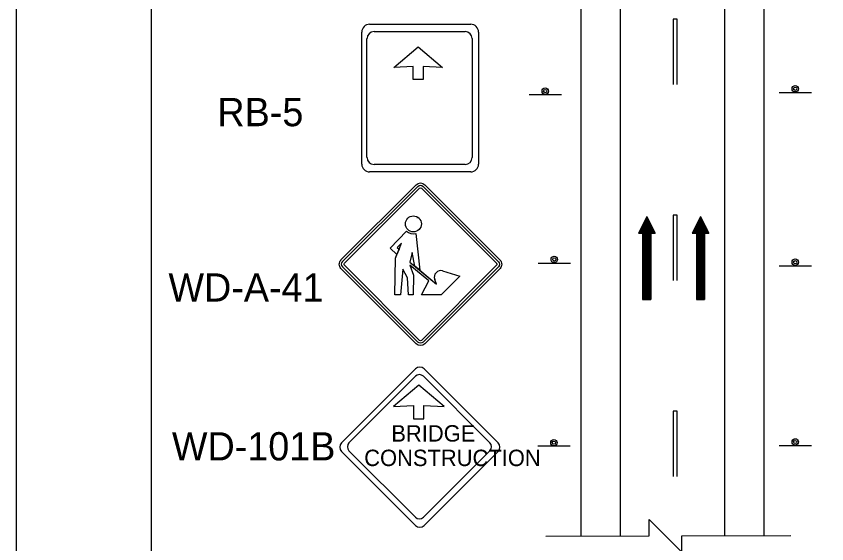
# Model space of a CAD drawing. Extents: x 2157 to 2399, y 147 to 426.
# Drawn here: x 2182.7 to 2242.8, y 199.6 to 238.6 of the extents above; entities that cross this region are included whole.
import ezdxf

# ---------------------------------------------------------------- set-up
doc = ezdxf.new("R2010")
doc.units = 0
for name, color, linetype in [('Level 1', 7, 'Continuous'), ('Level 10', 7, 'Continuous'), ('Level 20', 7, 'Continuous'), ('Level 44', 7, 'Continuous'), ('Level 60', 7, 'Continuous')]:
    doc.layers.add(name, color=color, linetype=linetype)

# ---------------------------------------------------------------- blocks, each defined once
blk = doc.blocks.new('2_95')
at = {"layer": 'Level 1'}
for points in [[(18.2, 120.1), (22.8, 116.1), (17.2, 102.4), (0, 118.7), (41.5, 161.7)], [(18.2, 120.1), (22.8, 116.1), (17.2, 102.4), (0, 118.7), (41.5, 161.7)], [(32.4, 65), (26.3, 0), (11.7, 0), (13.7, 93.4), (17.3, 102.4), (0, 118.7), (41.5, 161.7)], [(65.4, 155.5), (75, 62.6), (62.6, 72.8), (55.6, 107.5), (49.8, 83.3), (117.7, 27.3), (113, 39.4)], [(65.4, 155.5), (75, 62.6), (62.6, 72.8), (55.6, 107.5), (49.8, 83.3), (117.7, 27.3), (113, 39.4)], [(65.4, 155.5), (75, 62.5), (117.7, 27.3), (113, 39.4)], [(132.9, 60.9), (176.6, 47.8), (129.3, 0), (79.5, 0), (98.2, 36), (49.8, 75.6), (59.3, 50.4), (58, 0), (46.2, 0), (44, 43), (32.4, 65), (26.3, 0), (11.7, 0), (13.7, 93.4), (28.7, 130.9), (18.2, 120.1)], [(132.9, 60.9), (176.6, 47.8), (129.3, 0), (79.5, 0), (98.2, 36), (49.8, 75.6), (59.3, 50.4), (58, 0), (46.2, 0), (44, 43), (32.4, 65), (26.3, 0), (11.7, 0), (13.7, 93.4), (28.7, 130.9), (18.2, 120.1)], [(132.9, 60.9), (176.6, 47.8), (129.3, 0), (79.5, 0), (98.2, 36), (49.8, 75.6), (59.3, 50.4), (58, 0), (46.2, 0), (44, 43), (32.4, 65)]]:
    blk.add_lwpolyline(points, dxfattribs=at)
for points in [[(18.2, 120.1), (22.8, 116.1), (28.7, 130.9)], [(62.6, 72.8), (55.6, 107.5), (49.8, 83.3)]]:
    blk.add_lwpolyline(points, close=True, dxfattribs=at)
blk.add_circle((58.9, 179.8), 20.2, dxfattribs=at)
blk.add_circle((58.9, 179.8), 20.2, dxfattribs=at)
blk.add_circle((58.9, 179.8), 20.2, dxfattribs=at)
for centre, radius, start, end in [((58.9, 179.8), 25.1, 226.3135, 284.9576), ((58.9, 179.8), 25.1, 226.3135, 284.9576), ((58.9, 179.8), 25.1, 226.3135, 284.9576), ((128.2, 45.3), 16.3, 73.381, 201.0999), ((128.2, 45.3), 16.3, 73.381, 201.0999), ((128.2, 45.3), 16.3, 73.381, 201.0999)]:
    blk.add_arc(centre, radius, start, end, dxfattribs=at)
blk = doc.blocks.new('WDA41')
at = {"layer": 'Level 1'}
for p, q in [((-6.546, 0.348), (-0.352, 6.542)), ((-6.408, 0.21), (-0.215, 6.404)), ((-6.271, 0.073), (-0.077, 6.267)), ((0.072, 6.267), (6.27, 0.077)), ((0.21, 6.405), (6.408, 0.214)), ((0.348, 6.543), (6.545, 0.352)), ((0.287, 3.829), (0.303, 3.829)), ((-0.348, -6.542), (-6.546, -0.352)), ((-0.211, -6.404), (-6.408, -0.214)), ((-0.073, -6.266), (-6.27, -0.076)), ((6.27, -0.072), (0.076, -6.266)), ((6.408, -0.21), (0.214, -6.404)), ((6.546, -0.348), (0.352, -6.542))]:
    blk.add_line(p, q, dxfattribs=at)
for centre, radius, start, end in [((-0.002, 6.192), 0.495, 45.03492, 135), ((-0.002, 6.192), 0.3, 45.03492, 135), ((-0.002, 6.192), 0.105, 45.03492, 135), ((-6.196, -0.002), 0.495, 135, 225.03489), ((-6.196, -0.002), 0.3, 135, 225.03489), ((-6.196, -0.002), 0.105, 135, 225.03489), ((6.195, 0.002), 0.105, 315, 45.035), ((6.195, 0.002), 0.3, 315, 45.035), ((6.195, 0.002), 0.495, 315, 45.035), ((0.002, -6.192), 0.495, 225.03483, 315), ((0.002, -6.192), 0.3, 225.03483, 315), ((0.002, -6.192), 0.105, 225.03483, 315)]:
    blk.add_arc(centre, radius, start, end, dxfattribs=at)
at = {"layer": 'Level 1', "xscale": 0.032498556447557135, "yscale": -0.032498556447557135, "rotation": 180}
blk.add_blockref('2_95', (2.5, -2.524), dxfattribs=at)
blk = doc.blocks.new('APRNTR')
at = {"layer": 'Level 60'}
for points in [[(19.126, 268.191), (-196.874, 268.191), (-196.874, -10.809), (19.126, -10.809)], [(0, 257.382), (-186.874, 257.382), (-186.874, 0), (0, 0)]]:
    blk.add_lwpolyline(points, close=True, dxfattribs=at)

msp = doc.modelspace()

# ---------------------------------------------------------------- linework, layer by layer
at = {"layer": 'Level 10'}
for p, q in [((2224.589, 200.123), (2224.589, 338.668)), ((2238.136, 200.147), (2238.136, 338.668)), ((2227.492, 236.238), (2227.492, 302.984)), ((2235.233, 236.251), (2235.233, 284.274)), ((2231.401, 238.396), (2231.401, 233.558)), ((2231.691, 238.396), (2231.401, 238.396)), ((2231.691, 233.558), (2231.691, 238.396)), ((2227.492, 200.129), (2227.492, 236.238)), ((2235.233, 200.142), (2235.233, 236.257)), ((2229.438, 223.776), (2228.824, 222.548)), ((2229.283, 223.468), (2229.283, 217.64)), ((2229.361, 223.622), (2229.361, 217.64)), ((2229.438, 223.776), (2229.438, 217.64)), ((2229.438, 223.776), (2230.051, 222.548)), ((2229.514, 223.622), (2229.514, 217.64)), ((2229.591, 223.468), (2229.591, 217.64)), ((2231.401, 223.882), (2231.401, 219.044)), ((2231.691, 223.882), (2231.401, 223.882)), ((2231.691, 219.044), (2231.691, 223.882)), ((2233.422, 223.776), (2232.809, 222.548)), ((2233.268, 223.468), (2233.268, 217.64)), ((2233.346, 223.622), (2233.346, 217.64)), ((2233.422, 223.776), (2233.422, 217.64)), ((2233.422, 223.776), (2234.035, 222.548)), ((2233.498, 223.622), (2233.498, 217.64)), ((2233.575, 223.468), (2233.575, 217.64)), ((2228.977, 222.855), (2228.977, 222.548)), ((2229.054, 223.009), (2229.054, 222.548)), ((2229.131, 223.162), (2229.131, 217.64)), ((2229.208, 223.315), (2229.208, 217.64)), ((2229.668, 223.315), (2229.668, 217.64)), ((2229.744, 223.162), (2229.744, 217.64)), ((2229.821, 223.009), (2229.821, 222.548)), ((2229.898, 222.855), (2229.898, 222.548)), ((2232.961, 222.855), (2232.961, 222.548)), ((2233.038, 223.009), (2233.038, 222.548)), ((2233.116, 223.162), (2233.116, 217.64)), ((2233.192, 223.315), (2233.192, 217.64)), ((2233.652, 223.315), (2233.652, 217.64)), ((2233.729, 223.162), (2233.729, 217.64)), ((2233.806, 223.009), (2233.806, 222.548)), ((2233.882, 222.855), (2233.882, 222.548)), ((2228.824, 222.548), (2229.131, 222.548)), ((2228.901, 222.702), (2228.901, 222.548)), ((2229.131, 222.548), (2229.131, 217.64)), ((2229.744, 222.548), (2229.744, 217.64)), ((2229.744, 222.548), (2230.051, 222.548)), ((2229.974, 222.702), (2229.974, 222.548)), ((2232.809, 222.548), (2233.116, 222.548)), ((2232.885, 222.702), (2232.885, 222.548)), ((2233.116, 222.548), (2233.116, 217.64)), ((2233.729, 222.548), (2233.729, 217.64)), ((2233.729, 222.548), (2234.035, 222.548)), ((2233.959, 222.702), (2233.959, 222.548)), ((2229.131, 217.64), (2229.744, 217.64)), ((2233.116, 217.64), (2233.729, 217.64)), ((2231.401, 209.368), (2231.401, 204.53)), ((2231.691, 209.368), (2231.401, 209.368)), ((2231.691, 204.53), (2231.691, 209.368))]:
    msp.add_line(p, q, dxfattribs=at)
at = {"layer": 'Level 20'}
msp.add_lwpolyline([(2221.954, 200.119), (2229.617, 200.133), (2229.615, 201.342), (2230.827, 200.135), (2232.038, 198.927), (2232.036, 200.137), (2240.113, 200.151)], dxfattribs=at)
at = {"layer": 'Level 44'}
for p, q in [((2208.903, 238.008), (2216.399, 238.008)), ((2208.325, 227.659), (2208.325, 237.43)), ((2209.231, 237.469), (2215.977, 237.469)), ((2216.978, 237.43), (2216.978, 227.659)), ((2208.711, 228.154), (2208.711, 236.948)), ((2216.499, 236.948), (2216.499, 228.154)), ((2223.122, 232.794), (2220.726, 232.794)), ((2239.239, 232.969), (2241.635, 232.969)), ((2208.325, 227.656), (2208.325, 227.659)), ((2208.711, 228.152), (2208.711, 228.154)), ((2215.977, 227.632), (2209.231, 227.632)), ((2216.399, 227.078), (2208.903, 227.078)), ((2221.384, 220.336), (2223.78, 220.336)), ((2239.239, 220.127), (2241.635, 220.127)), ((2212.304, 212.5), (2206.826, 207.031)), ((2218.421, 207.031), (2212.952, 212.5)), ((2207.375, 207.026), (2212.304, 211.949)), ((2212.887, 211.949), (2217.81, 207.026)), ((2212.546, 211.303), (2210.663, 209.717)), ((2214.427, 209.717), (2212.546, 211.303)), ((2210.663, 209.717), (2212.168, 209.798)), ((2212.168, 209.798), (2212.168, 208.793)), ((2212.923, 208.793), (2212.923, 209.798)), ((2212.923, 209.798), (2214.427, 209.717)), ((2212.168, 208.793), (2212.918, 208.793)), ((2223.765, 206.767), (2221.369, 206.767)), ((2239.239, 206.818), (2241.635, 206.818)), ((2206.826, 206.381), (2212.304, 200.906)), ((2206.831, 206.381), (2206.826, 206.381)), ((2212.304, 201.515), (2207.375, 206.442)), ((2217.81, 206.442), (2212.887, 201.515)), ((2212.952, 200.906), (2218.421, 206.381))]:
    msp.add_line(p, q, dxfattribs=at)
msp.add_lwpolyline([(2210.692, 234.814), (2212.501, 236.337), (2214.311, 234.814), (2212.863, 234.89), (2212.863, 233.925), (2212.139, 233.925), (2212.139, 234.89)], close=True, dxfattribs=at)
for centre, radius in [((2221.919, 233.062), 0.24), ((2221.919, 233.062), 0.12), ((2240.443, 233.237), 0.24), ((2240.443, 233.237), 0.12), ((2222.588, 220.604), 0.24), ((2222.588, 220.604), 0.12), ((2240.443, 220.395), 0.24), ((2240.443, 220.395), 0.12), ((2222.561, 207.036), 0.24), ((2240.443, 207.087), 0.24), ((2240.443, 207.087), 0.12), ((2222.561, 207.036), 0.12)]:
    msp.add_circle(centre, radius, dxfattribs=at)
for centre, radius, start, end in [((2208.904, 237.429), 0.578, 90, 179.99999), ((2216.399, 237.429), 0.578, 359.99999, 89.99999), ((2209.232, 236.947), 0.52, 90, 179.99999), ((2215.977, 236.947), 0.52, 359.99999, 89.99999), ((2208.904, 227.657), 0.578, 180, 269.99999), ((2209.232, 228.152), 0.52, 180, 269.99999), ((2215.977, 228.152), 0.52, 270, 359.99999), ((2216.399, 227.657), 0.578, 270, 359.99999), ((2212.626, 212.178), 0.458, 45, 135), ((2212.594, 211.659), 0.412, 45, 135), ((2207.153, 206.706), 0.458, 135, 224.99999), ((2207.668, 206.733), 0.412, 135, 224.99999), ((2217.519, 206.733), 0.412, 315, 45), ((2218.099, 206.706), 0.458, 315, 45), ((2212.594, 201.808), 0.412, 225, 315), ((2212.626, 201.233), 0.458, 225, 315)]:
    msp.add_arc(centre, radius, start, end, dxfattribs=at)

# ---------------------------------------------------------------- block references
at = {"layer": 'Level 1', "xscale": 0.9, "yscale": -0.9, "rotation": 180}
msp.add_blockref('WDA41', (2212.675, 220.244), dxfattribs=at)
at = {"layer": 'Level 10'}
msp.add_blockref('APRNTR', (2379.594, 157.795), dxfattribs=at)

# ---------------------------------------------------------------- texts
for s, p in [('RB-5', (2197.626, 230.464)), ('WD-A-41', (2194, 217.481)), ('WD-101B', (2194.256, 205.722))]:
    msp.add_text(s, height=2.09, dxfattribs=at).set_placement(p)
at = {"layer": 'Level 44'}
for s, height, p in [('BRIDGE', 1.214, (2210.515, 207.116)), ('CONSTRUCTION', 1.21397, (2208.505, 205.302))]:
    msp.add_text(s, height=height, rotation=360, dxfattribs=at).set_placement(p)

doc.saveas('drawing.dxf')
